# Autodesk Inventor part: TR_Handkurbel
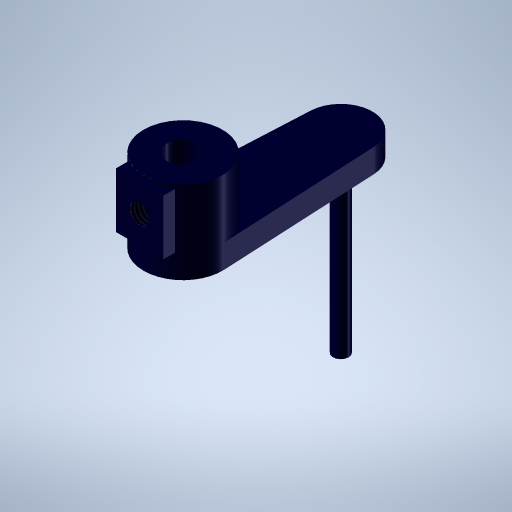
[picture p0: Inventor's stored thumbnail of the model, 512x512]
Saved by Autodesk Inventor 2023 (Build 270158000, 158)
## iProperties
Created: 2023-11
Part Number: TR_Handkurbel
Material: PC/ABS-Kunststoff
Document SubType Name: Modeling
Designer: Admin
Density: 0.357273 g/cm^3
Appearance: Glatt - marineblau
Author: Admin
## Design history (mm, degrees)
sketch "Skizze1"
  geometry: L1 (4.994, -0.25)-(3.995, -20.2); L2 (-3.995, -20.2)-(-4.994, -0.25); A1 r 5 centre (0, 0) between (4.994, -0.25) and (-4.994, -0.25); A2 r 4 centre (0, -20) between (-3.995, -20.2) and (3.995, -20.2); 1 further point
  constraints: 4 end point, 4 point on circle, 4 tangent, 2 centre point, 1 coincident, 1 vertical alignment
  dimensions: "d0" = 5 radius of A1 (= 0.5 x Einheitsmaß); "d1" = 20 distance of A2.centre point (0, 0) (= 2 x Einheitsmaß); "d2" = 4 radius of A2
extrude "Extrusion1" new body sketch "Skizze1" distance "d3" = 3; taper "d4" = 0 deg
sketch "Skizze2"
  geometry: C1 r 5 at (0, 0); A1 r 5 centre (0, 0) between (-4.994, 0.25) and (4.994, 0.25) reference; 1 further point
  constraints: 1 centre point, 1 coincident, 1 concentric
extrude "Extrusion2" join sketch "Skizze2" distance "d5" = 7.5; taper "d6" = 0 deg
sketch "Skizze3"
  geometry: L1 (3.995, 3)-(-3.995, 3) reference; L2 (-3, 3)-(3, 3); L3 (3, 3)-(3, 10); L4 (3, 10)-(-3, 10); L5 (-3, 10)-(-3, 3); L6 (5, 0)-(-5, 0) reference; 6 further points
  constraints: 8 end point, 2 midpoint, 2 parallel, 1 horizontal, 1 perpendicular, 1 point on line, 1 vertical alignment
  dimensions: "d7" = 7 distance of L2.end L3.end; "d8" = 6 distance of L3.end L4.end
extrude "Extrusion3" join sketch "Skizze3" distance "d9" = 5.5; taper "d10" = 0 deg
sketch "Skizze4"
  geometry: L1 (3, 10)-(-3, 10) reference; L2 (-3, 10)-(3, 3); L3 (-4.994, 3)-(4.994, 3) reference; L4 (3, 3)-(3, 10) reference; 2 further points
  constraints: 2 end point, 2 point on line, 1 midpoint
hole "Bohrung1" sketch "Skizze4" at (0, 6.5) diameter "d11" = 2.459; stored, may be unused: countersink angle "d15" = 90 deg, drill point angle "d17" = 0 deg; dims "d12" = 5, "d13" = 4, "d14" = 2, "d16" = 5
sketch "Skizze5"
  geometry: C1 r 1 at (0, -20); A1 r 4 centre (0, -20) between (-3.995, -20.2) and (3.995, -20.2) reference; 1 further point
  constraints: 1 centre point, 1 coincident
  dimensions: "d18" = 2 diameter of C1
extrude "Extrusion4" join sketch "Skizze5" distance "d19" = 21.5; taper "d20" = 0 deg
sketch "Skizze6"
  geometry: 2 further points
  constraints: 1 coincident
hole "Bohrung2" sketch "Skizze6" at (0, 0) diameter "d21" = 4; stored, may be unused: countersink angle "d25" = 90 deg, drill point angle "d27" = 0 deg; dims "d22" = 5, "d23" = 4, "d24" = 2, "d26" = 5
node "Volumenkörper1"
other parameters: "Radius" = 2.075 [user parameter], "Fasen" = 0.5 [user parameter], "Dicke" = 0.8 [user parameter], "Breitloch" = 2 [user parameter], "Langloch" = 32 [user parameter]
